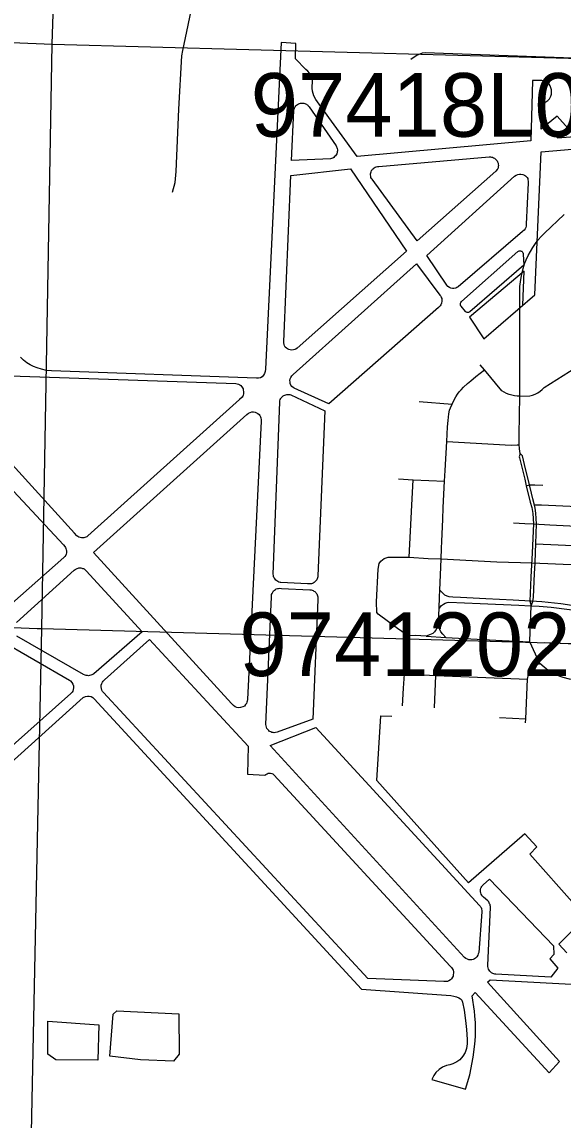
# Model space of a CAD drawing. Extents: x -157.2 to -99.3, y 12.2 to 46.2.
# Drawn here: x -147.776 to -146.84, y 29.245 to 31.144 of the extents above; entities that cross this region are included whole.
import ezdxf

# ---------------------------------------------------------------- set-up
doc = ezdxf.new("R2010")
doc.units = 0
for name, color, linetype in [('tdCoAirport', 7, 'Continuous'), ('tdCoCityStreetMajor', 7, 'Continuous'), ('tdCoCityStreetMinor', 7, 'Continuous'), ('tdCoHydroRiver', 7, 'Continuous'), ('tdCoSectLine', 7, 'Continuous'), ('tdCoStrucPriMaintName', 7, 'Continuous')]:
    doc.layers.add(name, color=color, linetype=linetype)

msp = doc.modelspace()

# ---------------------------------------------------------------- linework, layer by layer
at = {"layer": 'tdCoAirport'}
for points in [[(-146.7526, 30.9499), (-146.8498, 30.9426), (-146.8312, 30.9594), (-146.8503, 30.9809), (-146.8777, 30.9584), (-146.8772, 30.9887), (-146.8768, 30.9918), (-146.8759, 30.9946), (-146.8748, 30.9975), (-146.873, 31.0006), (-146.8713, 31.0033), (-146.8697, 31.0054), (-146.8662, 31.0079), (-146.8635, 31.0106), (-146.8613, 31.0152), (-146.86, 31.0189), (-146.8598, 31.0225), (-146.8601, 31.0264), (-146.8609, 31.0296), (-146.8623, 31.0329), (-146.8643, 31.0357), (-146.867, 31.0381), (-146.8702, 31.0401), (-146.8731, 31.0415), (-146.8765, 31.0421), (-146.8927, 31.0424), (-146.8958, 30.9377), (-147.1963, 30.9111), (-147.2622, 31.0013), (-147.2676, 31.0095), (-147.2709, 31.016), (-147.2722, 31.0196), (-147.2734, 31.0241), (-147.2738, 31.0288), (-147.2738, 31.0337), (-147.2734, 31.0378), (-147.2736, 31.0425), (-147.2742, 31.046), (-147.2753, 31.0493), (-147.2766, 31.0522), (-147.2785, 31.0549), (-147.2814, 31.0582), (-147.2849, 31.0616), (-147.3027, 31.0795), (-147.3026, 31.1065), (-147.3276, 31.1082), (-147.3546, 30.5432), (-147.3552, 30.5393), (-147.3566, 30.5355), (-147.3583, 30.5326), (-147.3607, 30.5301), (-147.3635, 30.5283), (-147.367, 30.5277), (-147.3703, 30.5273), (-147.725, 30.54), (-147.7338, 30.541), (-147.7421, 30.543), (-147.7497, 30.5453), (-147.7564, 30.5479), (-147.7619, 30.5507), (-147.7675, 30.5543), (-147.7735, 30.5588), (-147.7788, 30.5636)], [(-147.31, 30.9041), (-147.3056, 30.9903), (-147.3053, 30.9925), (-147.3046, 30.9946), (-147.3036, 30.9965), (-147.3024, 30.9983), (-147.3011, 30.9997), (-147.2995, 31.0009), (-147.2979, 31.0019), (-147.2961, 31.0026), (-147.2944, 31.003), (-147.2924, 31.0034), (-147.2904, 31.0033), (-147.2887, 31.0031), (-147.2868, 31.0026), (-147.2854, 31.0021), (-147.2841, 31.0014), (-147.2828, 31.0005), (-147.2817, 30.9995), (-147.2807, 30.9986), (-147.2795, 30.9968), (-147.2327, 30.9292), (-147.2318, 30.9277), (-147.2312, 30.9264), (-147.2308, 30.9246), (-147.2304, 30.9225), (-147.2304, 30.9209), (-147.2306, 30.9187), (-147.2309, 30.9171), (-147.2316, 30.9155), (-147.2325, 30.9136), (-147.2337, 30.9119), (-147.2352, 30.9106), (-147.2365, 30.9093), (-147.2383, 30.9082), (-147.2404, 30.9074), (-147.2426, 30.907), (-147.31, 30.9041)], [(-146.9095, 30.6535), (-146.9072, 30.7125), (-147.0018, 30.6328), (-146.9768, 30.5954), (-146.8888, 30.6714), (-146.8779, 30.9188), (-146.7503, 30.9299)], [(-147.0924, 30.765), (-147.1705, 30.8715), (-147.1715, 30.873), (-147.1723, 30.8748), (-147.1727, 30.8769), (-147.173, 30.8789), (-147.1729, 30.8808), (-147.1727, 30.8828), (-147.172, 30.8846), (-147.1712, 30.8864), (-147.1704, 30.8878), (-147.1695, 30.889), (-147.1682, 30.8901), (-147.167, 30.8912), (-147.1651, 30.8922), (-147.1631, 30.8929), (-147.1608, 30.8935), (-147.1588, 30.8937), (-146.9679, 30.9101), (-146.9656, 30.9102), (-146.9639, 30.91), (-146.9619, 30.9095), (-146.9602, 30.9088), (-146.9587, 30.9081), (-146.9573, 30.907), (-146.9561, 30.9059), (-146.9549, 30.9046), (-146.9539, 30.9032), (-146.9532, 30.9016), (-146.9525, 30.8995), (-146.9521, 30.8975), (-146.9519, 30.8954), (-146.952, 30.8938), (-146.9525, 30.8914), (-146.9531, 30.8898), (-146.954, 30.8883), (-146.9562, 30.8858), (-147.0924, 30.7651)], [(-147.1111, 30.7471), (-147.3, 30.5793), (-147.3021, 30.5779), (-147.3039, 30.5772), (-147.3063, 30.5766), (-147.309, 30.5762), (-147.3119, 30.5763), (-147.3145, 30.5769), (-147.317, 30.578), (-147.3187, 30.5795), (-147.3205, 30.5814), (-147.3219, 30.5837), (-147.3227, 30.5859), (-147.3233, 30.5884), (-147.3233, 30.5912), (-147.3107, 30.8778), (-147.2078, 30.8898), (-147.1111, 30.7471)], [(-147.0758, 30.7394), (-146.9238, 30.8769), (-146.9212, 30.8785), (-146.9181, 30.8799), (-146.9153, 30.8805), (-146.9129, 30.8803), (-146.9097, 30.8796), (-146.9069, 30.8784), (-146.9049, 30.8772), (-146.9033, 30.8758), (-146.9021, 30.8744), (-146.9012, 30.8726), (-146.9007, 30.8708), (-146.9002, 30.8684), (-146.9002, 30.8656), (-146.904, 30.7936), (-146.9041, 30.7902), (-146.9046, 30.7882), (-146.9057, 30.7857), (-146.9072, 30.7837), (-146.9101, 30.7809), (-147.0212, 30.6854), (-147.0235, 30.6842), (-147.0257, 30.6831), (-147.0287, 30.6827), (-147.0313, 30.6826), (-147.0342, 30.6833), (-147.0366, 30.6844), (-147.0393, 30.6861), (-147.0413, 30.6881), (-147.0758, 30.7394)], [(-147.009, 30.6431), (-147.0163, 30.6519), (-147.0172, 30.6531), (-147.0176, 30.6545), (-147.0176, 30.6559), (-147.0172, 30.6574), (-147.0167, 30.6586), (-147.0155, 30.6599), (-146.9185, 30.7465), (-146.9173, 30.7472), (-146.9161, 30.7476), (-146.915, 30.7478), (-146.9138, 30.7477), (-146.9126, 30.7474), (-146.9116, 30.7469), (-146.9108, 30.7463), (-146.9101, 30.7455), (-146.9095, 30.7446), (-146.9091, 30.7433), (-146.909, 30.742), (-146.908, 30.723), (-147.0014, 30.642), (-147.0023, 30.6414), (-147.0034, 30.6411), (-147.0043, 30.641), (-147.0053, 30.641), (-147.0061, 30.6411), (-147.007, 30.6414), (-147.0078, 30.6419), (-147.009, 30.6431)], [(-147.0936, 30.7251), (-147.053, 30.671), (-147.0517, 30.6692), (-147.0508, 30.6673), (-147.05, 30.6653), (-147.0496, 30.6628), (-147.0495, 30.6607), (-147.0501, 30.6572), (-147.0513, 30.6544), (-147.0524, 30.6529), (-147.0555, 30.6498), (-147.2453, 30.4833), (-147.3052, 30.51), (-147.3072, 30.5113), (-147.3092, 30.5133), (-147.3108, 30.5157), (-147.3119, 30.5184), (-147.3124, 30.521), (-147.3125, 30.5235), (-147.312, 30.5263), (-147.311, 30.5288), (-147.3093, 30.5313), (-147.3069, 30.5337), (-147.0936, 30.7251)], [(-147.8645, 30.5339), (-147.4062, 30.5182), (-147.404, 30.5179), (-147.4016, 30.5171), (-147.3994, 30.5159), (-147.3976, 30.5147), (-147.3955, 30.5126), (-147.3944, 30.5109), (-147.3937, 30.5089), (-147.3932, 30.5067), (-147.3928, 30.5046), (-147.3929, 30.5024), (-147.3931, 30.5005), (-147.3935, 30.4981), (-147.3943, 30.4962), (-147.3953, 30.4948), (-147.3999, 30.4907), (-147.6623, 30.2549), (-147.6641, 30.2533), (-147.6655, 30.2527), (-147.6673, 30.252), (-147.6693, 30.2514), (-147.6714, 30.2513), (-147.6733, 30.2512), (-147.6756, 30.2518), (-147.6776, 30.2525), (-147.6796, 30.2537), (-147.6815, 30.2547), (-147.6854, 30.2594), (-147.8956, 30.4907)], [(-147.2519, 30.4713), (-147.2643, 30.1859), (-147.2644, 30.1837), (-147.2647, 30.1823), (-147.2652, 30.1806), (-147.266, 30.1789), (-147.2669, 30.1776), (-147.2681, 30.1763), (-147.2694, 30.1751), (-147.2708, 30.1739), (-147.2722, 30.1732), (-147.2737, 30.1725), (-147.2754, 30.172), (-147.2773, 30.1717), (-147.2821, 30.1718), (-147.3281, 30.1741), (-147.3297, 30.1744), (-147.3315, 30.1748), (-147.3334, 30.1756), (-147.3353, 30.1768), (-147.3368, 30.1782), (-147.3383, 30.1797), (-147.3394, 30.1815), (-147.3402, 30.183), (-147.3407, 30.1848), (-147.3411, 30.1864), (-147.3413, 30.1884), (-147.3302, 30.4862), (-147.3298, 30.4885), (-147.3292, 30.4905), (-147.3283, 30.4921), (-147.3275, 30.4936), (-147.3264, 30.4949), (-147.3255, 30.4958), (-147.3242, 30.4969), (-147.3229, 30.4976), (-147.3215, 30.4983), (-147.3194, 30.4989), (-147.3177, 30.4993), (-147.3161, 30.4994), (-147.3143, 30.4994), (-147.3125, 30.4991), (-147.3108, 30.4985), (-147.2519, 30.4713)], [(-147.6525, 30.2258), (-147.3871, 30.4647), (-147.3842, 30.4672), (-147.3816, 30.4683), (-147.3787, 30.4691), (-147.3758, 30.4692), (-147.3725, 30.4687), (-147.3704, 30.4676), (-147.3681, 30.4663), (-147.3659, 30.4646), (-147.3648, 30.463), (-147.3636, 30.4608), (-147.363, 30.4589), (-147.3625, 30.4557), (-147.3625, 30.4529), (-147.386, 29.9717), (-147.3864, 29.969), (-147.387, 29.9669), (-147.3878, 29.9649), (-147.3892, 29.9631), (-147.3913, 29.9604), (-147.394, 29.9591), (-147.3978, 29.9579), (-147.4011, 29.9574), (-147.4042, 29.9579), (-147.4073, 29.9592), (-147.4103, 29.9614), (-147.4134, 29.9646), (-147.6525, 30.2258)], [(-147.7983, 30.3404), (-147.704, 30.2391), (-147.7018, 30.2365), (-147.7008, 30.2349), (-147.7, 30.2332), (-147.6995, 30.2308), (-147.6993, 30.2292), (-147.6991, 30.2273), (-147.6992, 30.2256), (-147.6995, 30.2234), (-147.7004, 30.2214), (-147.7017, 30.2191), (-147.7035, 30.2171), (-147.7935, 30.1379)], [(-147.7856, 30.1048), (-147.6858, 30.1955), (-147.6842, 30.1966), (-147.6827, 30.1974), (-147.6807, 30.1984), (-147.6791, 30.1989), (-147.6775, 30.1993), (-147.676, 30.1994), (-147.6743, 30.1993), (-147.6727, 30.1991), (-147.6713, 30.1986), (-147.6699, 30.1981), (-147.6687, 30.1975), (-147.6674, 30.1967), (-147.6662, 30.1957), (-147.665, 30.1945), (-147.5679, 30.0889)], [(-147.2729, 29.9375), (-147.3348, 29.9152), (-147.3375, 29.9146), (-147.3396, 29.9144), (-147.3417, 29.9146), (-147.3438, 29.9149), (-147.3457, 29.9157), (-147.3477, 29.9167), (-147.3493, 29.9181), (-147.3509, 29.9197), (-147.3523, 29.9217), (-147.3532, 29.9239), (-147.3538, 29.926), (-147.354, 29.9288), (-147.3446, 30.1494), (-147.3446, 30.1513), (-147.3442, 30.1531), (-147.3435, 30.1554), (-147.3424, 30.1573), (-147.3407, 30.1595), (-147.3394, 30.1607), (-147.3377, 30.162), (-147.3362, 30.1629), (-147.3342, 30.1636), (-147.3323, 30.164), (-147.3301, 30.1641), (-147.3273, 30.164), (-147.2781, 30.1616), (-147.2757, 30.1615), (-147.2739, 30.161), (-147.2724, 30.1604), (-147.2709, 30.1594), (-147.2693, 30.1583), (-147.268, 30.157), (-147.2669, 30.1558), (-147.2661, 30.1546), (-147.2652, 30.153), (-147.2647, 30.1513), (-147.2644, 30.1495), (-147.2642, 30.1475), (-147.2644, 30.1444), (-147.2729, 29.9375)], [(-147.5679, 30.0889), (-147.6518, 30.0164), (-147.6536, 30.0152), (-147.6555, 30.0143), (-147.6571, 30.0136), (-147.6592, 30.0132), (-147.6613, 30.013), (-147.6627, 30.0131), (-147.6648, 30.0132), (-147.6669, 30.0137), (-147.6695, 30.0149), (-147.7848, 30.0815)], [(-147.8177, 30.0767), (-147.6938, 30.0051), (-147.6924, 30.0042), (-147.6898, 30.0013), (-147.688, 29.9982), (-147.6871, 29.9954), (-147.6869, 29.9921), (-147.6874, 29.9889), (-147.6883, 29.9863), (-147.6894, 29.9843), (-147.6914, 29.9822), (-147.8144, 29.8734)], [(-147.5554, 30.0754), (-147.3848, 29.891), (-147.3858, 29.8429), (-147.3561, 29.8408), (-147.3544, 29.8422), (-147.3522, 29.8435), (-147.3502, 29.8442), (-147.3481, 29.8444), (-147.3461, 29.8442), (-147.3441, 29.8438), (-147.3421, 29.843), (-147.3403, 29.8414), (-147.0353, 29.5108), (-147.033, 29.5082), (-147.0317, 29.5064), (-147.0303, 29.5037), (-147.0298, 29.5012), (-147.0298, 29.4987), (-147.0299, 29.496), (-147.0303, 29.4936), (-147.0314, 29.4915), (-147.0332, 29.4889), (-147.035, 29.487), (-147.0376, 29.4853), (-147.04, 29.4843), (-147.0424, 29.4842), (-147.0461, 29.4843), (-147.1775, 29.489), (-147.6351, 29.9839), (-147.637, 29.9857), (-147.6379, 29.9879), (-147.6388, 29.9909), (-147.6392, 29.9938), (-147.639, 29.9968), (-147.6381, 29.9997), (-147.637, 30.0016), (-147.6356, 30.0036), (-147.6332, 30.0056), (-147.5554, 30.0754)], [(-147.8009, 29.8571), (-147.6704, 29.9751), (-147.6662, 29.9768), (-147.663, 29.9775), (-147.66, 29.9773), (-147.6566, 29.9767), (-147.6536, 29.9752), (-147.651, 29.9731), (-147.1885, 29.4707), (-147.0339, 29.4596), (-147.0287, 29.459), (-147.0242, 29.4577), (-147.0202, 29.4559), (-147.0175, 29.4541), (-147.0154, 29.4517), (-147.014, 29.4482), (-147.0111, 29.4344), (-147.0086, 29.4166), (-147.0073, 29.4013), (-147.0061, 29.3837), (-147.0058, 29.3764), (-147.007, 29.3685), (-147.0095, 29.3615), (-147.0132, 29.355), (-147.0187, 29.3487), (-147.0239, 29.3449), (-147.0307, 29.3416), (-147.036, 29.3397), (-147.0419, 29.3386), (-147.0483, 29.3357), (-147.0544, 29.3319), (-147.0602, 29.3266), (-147.0637, 29.3214), (-147.0673, 29.3147), (-147.0085, 29.2977), (-147.0012, 29.3228), (-146.9954, 29.353), (-146.9927, 29.3755), (-146.9916, 29.3888), (-146.9912, 29.3993), (-146.9916, 29.4129), (-146.9925, 29.4245), (-146.9933, 29.4327), (-146.9975, 29.4594), (-146.9923, 29.4652), (-146.864, 29.3259), (-146.846, 29.3456), (-146.9709, 29.4827), (-146.9661, 29.4872), (-146.815, 29.4789)], [(-146.8199, 29.6167), (-146.8976, 29.7041), (-146.8855, 29.7169), (-146.9062, 29.7393), (-147.0036, 29.6549), (-147.1619, 29.8317), (-147.1554, 29.9433), (-147.1364, 29.943)], [(-146.9804, 29.6044), (-146.986, 29.5344), (-146.9866, 29.5317), (-146.9877, 29.5294), (-146.9894, 29.5266), (-146.9913, 29.5247), (-146.9933, 29.5232), (-146.9954, 29.5222), (-146.998, 29.5216), (-147.0005, 29.5214), (-147.0031, 29.5216), (-147.0055, 29.5225), (-147.0083, 29.5237), (-147.0105, 29.5257), (-147.3468, 29.8922), (-147.268, 29.9233), (-146.9846, 29.6157), (-146.9836, 29.6144), (-146.9826, 29.6133), (-146.9818, 29.6118), (-146.9812, 29.6103), (-146.9809, 29.6091), (-146.9805, 29.6071), (-146.9805, 29.6055), (-146.9804, 29.6044)], [(-146.8613, 29.4918), (-146.9564, 29.4969), (-146.958, 29.497), (-146.9596, 29.4975), (-146.9616, 29.4981), (-146.9636, 29.4991), (-146.9653, 29.5006), (-146.9668, 29.5021), (-146.9679, 29.5038), (-146.9688, 29.5054), (-146.9696, 29.5078), (-146.97, 29.5099), (-146.97, 29.5126), (-146.9655, 29.6121), (-146.9656, 29.614), (-146.966, 29.6155), (-146.9664, 29.6172), (-146.967, 29.6187), (-146.9677, 29.6204), (-146.9685, 29.6216), (-146.9694, 29.6228), (-146.9704, 29.6238), (-146.9777, 29.6299), (-146.9792, 29.6312), (-146.98, 29.6323), (-146.9808, 29.6336), (-146.9816, 29.6351), (-146.9824, 29.6373), (-146.9828, 29.6388), (-146.9829, 29.6402), (-146.9829, 29.6418), (-146.9826, 29.6434), (-146.9821, 29.6453), (-146.9814, 29.6468), (-146.9805, 29.6484), (-146.9797, 29.6496), (-146.9784, 29.651), (-146.9673, 29.661), (-146.8566, 29.5459), (-146.8557, 29.5308), (-146.8629, 29.5235), (-146.8491, 29.5074), (-146.8613, 29.4918)], [(-146.8333, 29.5337), (-146.8472, 29.5486), (-146.8211, 29.5746)]]:
    msp.add_lwpolyline(points, dxfattribs=at)
at = {"layer": 'tdCoCityStreetMajor'}
for p, q in [((-146.976, 30.5418), (-146.9832, 30.5504)), ((-146.9144, 30.3971), (-146.9159, 30.3917)), ((-146.8806, 30.0336), (-146.8801, 30.0338))]:
    msp.add_line(p, q, dxfattribs=at)
for points in [[(-147.0511, 30.215), (-147.0503, 30.2327), (-147.0497, 30.2455), (-147.048, 30.2831), (-147.0474, 30.3038), (-147.0449, 30.3493), (-147.0437, 30.3678), (-147.0408, 30.418), (-147.04, 30.4431), (-147.0389, 30.4543), (-147.0376, 30.4656), (-147.0362, 30.4721), (-147.0347, 30.476), (-147.0321, 30.4823), (-147.0291, 30.489), (-147.0253, 30.4953), (-147.0224, 30.5), (-147.0196, 30.5041), (-147.0164, 30.5075), (-147.012, 30.512), (-147.0053, 30.5184), (-146.9996, 30.5231), (-146.991, 30.5302), (-146.976, 30.5417)], [(-146.9146, 30.4965), (-146.9193, 30.4965), (-146.9241, 30.497), (-146.9288, 30.4979), (-146.9334, 30.4992), (-146.9378, 30.5009), (-146.9421, 30.5031), (-146.9461, 30.5056), (-146.976, 30.5417), (-146.976, 30.5418)], [(-146.9143, 30.4965), (-146.8973, 30.4968), (-146.8927, 30.4982), (-146.8882, 30.5), (-146.8839, 30.5022), (-146.8798, 30.5048), (-146.876, 30.5078), (-146.8725, 30.5111), (-146.8072, 30.5528)], [(-146.9144, 30.3974), (-146.9153, 30.4054), (-146.9158, 30.4134), (-146.916, 30.4215), (-146.9158, 30.4295), (-146.9146, 30.4965), (-146.9146, 30.4981)], [(-146.9159, 30.3917), (-146.9155, 30.3895), (-146.9062, 30.3526), (-146.9037, 30.3415), (-146.897, 30.3131), (-146.894, 30.304), (-146.8923, 30.2937), (-146.8911, 30.2758), (-146.8937, 30.2256), (-146.8958, 30.1835), (-146.8974, 30.1418), (-146.8952, 30.1338)], [(-146.8952, 30.1338), (-146.8922, 30.1415), (-146.891, 30.1485), (-146.8893, 30.1898), (-146.8885, 30.2077), (-146.8876, 30.2267), (-146.8872, 30.2411), (-146.8862, 30.2755), (-146.887, 30.2939), (-146.8881, 30.3028), (-146.8898, 30.31), (-146.8922, 30.3188), (-146.8948, 30.3285), (-146.8982, 30.3431), (-146.9068, 30.3782), (-146.9101, 30.3931), (-146.9144, 30.3974)], [(-147.0556, 30.0997), (-147.0558, 30.1003), (-147.0548, 30.1181), (-147.0544, 30.1294), (-147.0538, 30.1491), (-147.0534, 30.1609), (-147.0529, 30.1743), (-147.0517, 30.2006), (-147.0511, 30.215)], [(-146.8953, 30.1417), (-146.8963, 30.1417), (-146.9264, 30.1433), (-146.9737, 30.1461), (-147.0174, 30.1482), (-147.0309, 30.1488), (-147.0369, 30.1494), (-147.0405, 30.1503), (-147.0443, 30.1524), (-147.0477, 30.1552), (-147.0534, 30.1609)], [(-147.0544, 30.1294), (-147.0502, 30.1341), (-147.0467, 30.1367), (-147.044, 30.1383), (-147.0405, 30.1396), (-147.0377, 30.1402), (-146.9833, 30.138), (-146.9168, 30.1348), (-146.8965, 30.1338), (-146.8952, 30.1338)], [(-146.7611, 30.1231), (-146.7968, 30.1291), (-146.8173, 30.133), (-146.8441, 30.1374), (-146.8765, 30.1407), (-146.8953, 30.1417)], [(-146.8973, 30.0718), (-146.8977, 30.0726), (-146.8952, 30.1338)], [(-146.8952, 30.1338), (-146.8816, 30.1331), (-146.8603, 30.1313), (-146.8287, 30.1273), (-146.7951, 30.1213), (-146.7599, 30.1152)], [(-146.4081, 29.1299), (-146.5073, 29.3473), (-146.604, 29.5616), (-146.6828, 29.7364), (-146.7181, 29.8139), (-146.7291, 29.844), (-146.7395, 29.8795), (-146.7427, 29.8974), (-146.7443, 29.9132), (-146.7443, 29.9371), (-146.7471, 29.9519), (-146.7531, 29.9652), (-146.7591, 29.9756), (-146.7704, 29.9869), (-146.7849, 29.9967), (-146.7994, 30.0033), (-146.8142, 30.0061), (-146.8287, 30.0068), (-146.84, 30.0096), (-146.8514, 30.0137), (-146.8618, 30.0187), (-146.8801, 30.0338), (-146.8813, 30.0364)]]:
    msp.add_lwpolyline(points, dxfattribs=at)
at = {"layer": 'tdCoCityStreetMinor'}
for p, q in [((-147.0892, 30.4873), (-147.0321, 30.4823)), ((-146.9146, 30.4965), (-146.9143, 30.4965)), ((-146.9178, 30.4121), (-146.9158, 30.4122)), ((-146.9037, 30.3415), (-146.9036, 30.3415)), ((-146.8872, 30.2411), (-146.7573, 30.2349)), ((-147.0769, 30.0812), (-147.0766, 30.0811)), ((-147.0766, 30.0811), (-147.043, 30.0788)), ((-146.8813, 30.0364), (-146.8973, 30.0718)), ((-147.0626, 29.9573), (-147.0604, 30.0133)), ((-146.9501, 29.9405), (-146.9048, 29.9384))]:
    msp.add_line(p, q, dxfattribs=at)
for points in [[(-147.5156, 30.8494), (-147.5112, 30.8662), (-147.5092, 30.8847), (-147.5048, 30.9925), (-147.4998, 31.0852), (-147.4981, 31.0943), (-147.4788, 31.1853), (-147.4721, 31.2072), (-147.463, 31.2312), (-147.4359, 31.2906), (-147.4196, 31.3273), (-147.4115, 31.3461), (-147.407, 31.3586), (-147.4041, 31.3722), (-147.3996, 31.4053), (-147.3925, 31.4689), (-147.3804, 31.5675), (-147.3792, 31.5737), (-147.3753, 31.5863)], [(-147.1033, 31.0794), (-147.0939, 31.0856), (-147.0833, 31.0903), (-147.0784, 31.0908), (-146.7914, 31.0806), (-146.7029, 31.0775)], [(-146.9146, 30.4988), (-146.915, 30.6255), (-146.9148, 30.6779), (-146.9145, 30.6859), (-146.9138, 30.6939), (-146.9127, 30.7018), (-146.911, 30.7097), (-146.909, 30.7174), (-146.9065, 30.725), (-146.9036, 30.7324), (-146.9002, 30.7397), (-146.8965, 30.7468), (-146.8923, 30.7536), (-146.8878, 30.7602), (-146.8829, 30.7665), (-146.8776, 30.7725), (-146.872, 30.7782), (-146.8381, 30.8105)], [(-147.0408, 30.418), (-146.93, 30.4118), (-146.9193, 30.412), (-146.9178, 30.4121)], [(-147.1246, 30.3533), (-147.0993, 30.3518), (-147.0449, 30.3493)], [(-147.1064, 30.2177), (-147.1014, 30.3076), (-147.0993, 30.3518)], [(-146.9036, 30.3415), (-146.8982, 30.3431), (-146.8889, 30.3432), (-146.875, 30.3422)], [(-146.8893, 30.3082), (-146.8772, 30.3087), (-146.7541, 30.3028)], [(-146.9256, 30.2772), (-146.906, 30.2762), (-146.8911, 30.2758)], [(-146.8911, 30.2758), (-146.8626, 30.2736), (-146.8169, 30.2714), (-146.756, 30.2693)], [(-147.0769, 30.0812), (-147.0953, 30.0823), (-147.105, 30.0819), (-147.1116, 30.0841), (-147.1265, 30.0947), (-147.1598, 30.1191), (-147.1623, 30.1222), (-147.1626, 30.1409), (-147.1596, 30.1972), (-147.158, 30.2069), (-147.1553, 30.2111), (-147.1496, 30.2156), (-147.1423, 30.2179), (-147.1333, 30.2182), (-147.1064, 30.2177)], [(-147.1064, 30.2177), (-147.0733, 30.2159), (-147.0511, 30.215)], [(-147.0511, 30.215), (-146.9543, 30.2097), (-146.8934, 30.2079), (-146.759, 30.2022)], [(-147.0558, 30.1003), (-147.0565, 30.099), (-147.0583, 30.095), (-147.0596, 30.0927), (-147.0611, 30.0904), (-147.0625, 30.0887), (-147.0642, 30.0872), (-147.0655, 30.0862), (-147.0684, 30.0845), (-147.0769, 30.0812)], [(-147.043, 30.0788), (-147.0478, 30.0846), (-147.0512, 30.089), (-147.0533, 30.0927), (-147.0547, 30.0971), (-147.0556, 30.0997)], [(-147.1176, 29.9607), (-147.1158, 29.9912), (-147.1145, 30.0157), (-147.1145, 30.0164), (-147.1124, 30.0755)], [(-147.043, 30.0788), (-146.9455, 30.0741), (-146.8973, 30.0718)], [(-146.8721, 30.0706), (-146.831, 30.0686), (-146.8033, 30.0676), (-146.7612, 30.0668), (-146.7414, 30.0653)], [(-146.9016, 30.0072), (-146.9016, 30.0072), (-146.8999, 30.0153), (-146.8977, 30.0222), (-146.8942, 30.0269), (-146.8889, 30.0317), (-146.8806, 30.0336)], [(-147.1145, 30.0164), (-147.0604, 30.0133), (-146.9016, 30.0072)], [(-146.9047, 29.9316), (-146.9044, 29.9384), (-146.9016, 30.0072)]]:
    msp.add_lwpolyline(points, dxfattribs=at)
at = {"layer": 'tdCoHydroRiver'}
for points in [[(-147.5708, 29.3484), (-147.6242, 29.3549), (-147.6186, 29.4274), (-147.6121, 29.4335), (-147.5049, 29.4282), (-147.5041, 29.3587), (-147.514, 29.3464), (-147.5708, 29.3484)], [(-147.7176, 29.3487), (-147.7314, 29.3586), (-147.7311, 29.4155), (-147.6429, 29.4093), (-147.645, 29.3478), (-147.7176, 29.3487)]]:
    msp.add_lwpolyline(points, dxfattribs=at)
at = {"layer": 'tdCoSectLine'}
for points in [[(-147.7238, 31.1053), (-147.6908, 32.0994)], [(-148.7009, 31.1454), (-147.7238, 31.1053)], [(-147.7418, 30.0945), (-147.7238, 31.1053)], [(-147.7238, 31.1053), (-146.7032, 31.0775)], [(-148.7918, 30.1376), (-147.7499, 30.0944), (-147.7418, 30.0945)], [(-147.7617, 29.1108), (-147.7418, 30.0945)], [(-147.7418, 30.0945), (-146.7417, 30.0665)]]:
    msp.add_lwpolyline(points, dxfattribs=at)

# ---------------------------------------------------------------- texts
at = {"layer": 'tdCoStrucPriMaintName'}
for s, p in [('97418L029', (-147.3803, 30.9451)), ('97412029', (-147.3999, 30.0123))]:
    msp.add_text(s, height=0.11, dxfattribs=at).set_placement(p)

doc.saveas('drawing.dxf')
